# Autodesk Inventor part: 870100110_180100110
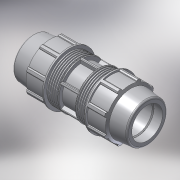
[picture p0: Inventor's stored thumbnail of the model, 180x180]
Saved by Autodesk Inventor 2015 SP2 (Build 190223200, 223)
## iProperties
Created: 2017-02
Part Number: 870100110_180100110
Material: PVC-Piping
Description: PLASSON COUPLER 110-110
Document SubType Name: Modeling
Designer: KIM
Mass: 2387.75 g
Surface Area: 2478.17 cm^2
Volume: 1705.54 cm^3
Density: 1.4 g/cm^3
Appearance: Smooth - White
Author: KIM
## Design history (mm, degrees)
derived "87010.ipt"
feature "Solid1::87010.ipt"
tag "TaggingFeature1"
body "Solid1"
other parameters: "d1" = 398, "d4" = 33.16667, "d5" = 56.85714, "d7" = 181, "d8" = 135.75, "d9" = 56.85714, "d11" = 5.68571, "d12" = 144.8, "d13" = 120 deg, "d14" = 143, "d15" = 6 deg, "d16" = 162.9, "d18" = 5.5, "d19" = 35 deg, "d20" = 17.5 deg, "d21" = 168.33, "d23" = 0, "d25" = 360 deg, "d27" = 3.62, "d33" = 2.2, "d34" = 9.05, "d36" = 0, "d37" = 2.2, "d38" = 2.2, "d40" = 360 deg, "d42" = 71.64, "d46" = 3.3, "d50" = 4.975, "d51" = 0, "d53" = 3.63886, "d54" = 3.63886, "d57" = 7.27771, "d62" = 159.642, "d64" = 99, "d65" = 196, "E_" = 181, "H_" = 398, "l_" = 196, "d52" = 36.38857
